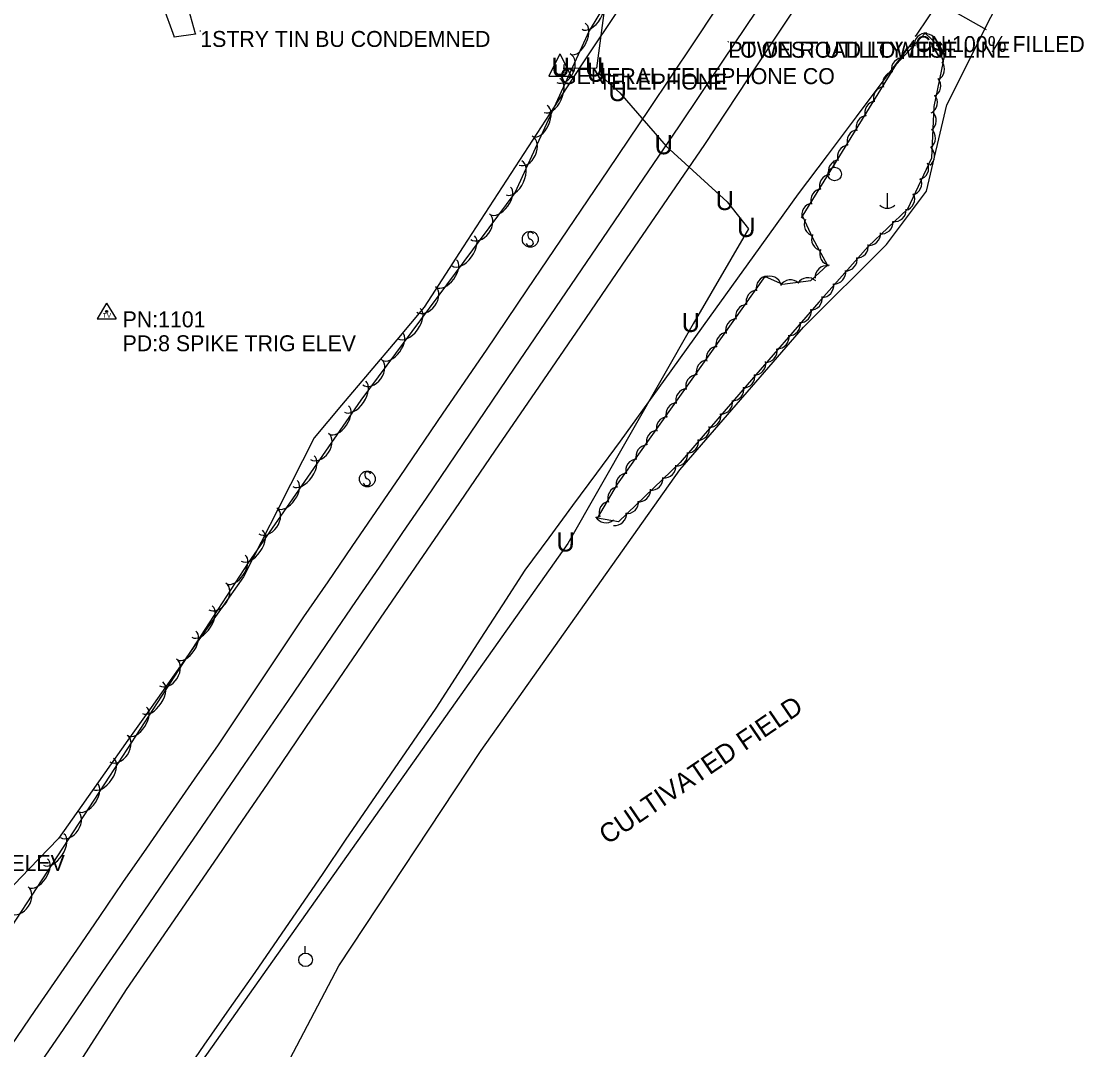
# Model space of a CAD drawing. Extents: x 1451369 to 1458940, y 1868647 to 1875095.
# Drawn here: x 1454865 to 1455198.2, y 1872001.9 to 1872324.4 of the extents above; entities that cross this region are included whole.
import ezdxf

# ---------------------------------------------------------------- set-up
doc = ezdxf.new("R2010")
doc.units = 0
for name, color, linetype in [('Default', 7, 'Continuous'), ('E_Const Align', 7, 'Continuous'), ('E_No Plot', 7, 'Continuous'), ('E_PL and Hook', 7, 'Continuous'), ('E_Property Line', 7, 'Continuous'), ('E_Proposed ROW and Easements', 7, 'Continuous'), ('E_Row Point', 7, 'Continuous'), ('E_ROW Point Number', 7, 'Continuous'), ('E_Station Offset', 7, 'Continuous'), ('E_Survey Point Number', 7, 'Continuous'), ('E_Tract Number', 7, 'Continuous'), ('S_EDGE_PAVEMENT', 7, 'Continuous'), ('S_ELECTRIC_UTILITIES_ANNOT', 7, 'Continuous'), ('S_EXIST_ROW', 7, 'Continuous'), ('S_MISC_BOUNDARY', 7, 'Continuous'), ('S_MISC_BOUNDARY_ANNOT', 7, 'Continuous'), ('S_PAVEMENT_CROWN', 7, 'Continuous'), ('S_SECONDARY_CTL_ANNOT', 7, 'Continuous'), ('S_SIDE_DRAIN_ANNOT', 7, 'Continuous'), ('S_SIGN', 7, 'Continuous'), ('S_SURVEY_TEXT_ANNOT', 7, 'Continuous'), ('S_TRAILS', 7, 'Continuous'), ('S_UNDERGROUND_CABLE_ANNOT', 7, 'Continuous'), ('S_UTILITY_POLE_ANNOT', 7, 'Continuous')]:
    doc.layers.add(name, color=color, linetype=linetype)

msp = doc.modelspace()

# ---------------------------------------------------------------- linework, layer by layer
at = {"layer": 'E_Const Align'}
for p, q in [((1455119.98, 1872278.62), (1455119.98, 1872280.72)), ((1455136.55, 1872270.43), (1455136.55, 1872265.7)), ((1454954.04, 1872032.19), (1454954.04, 1872034.3))]:
    msp.add_line(p, q, dxfattribs=at)
for centre in [(1455120.1, 1872276.47), (1454954.16, 1872030.05)]:
    msp.add_circle(centre, 2.13, dxfattribs=at)
msp.add_arc((1455136.61, 1872269.13), 3.41, 226.3972, 313.6028, dxfattribs=at)
at = {"layer": 'E_No Plot'}
msp.add_lwpolyline([(1455086.75, 1872317.95), (1455086.75, 1872318), (1455086.75, 1872317.95), (1455086.7, 1872317.95), (1455086.75, 1872317.95), (1455086.75, 1872317.9), (1455086.75, 1872317.95), (1455086.8, 1872317.95)], dxfattribs=at)
at = {"layer": 'E_PL and Hook'}
msp.add_line((1455157.21, 1872337.28), (1455145.4, 1872319.72), dxfattribs=at)
at = {"layer": 'E_Property Line'}
for p, q in [((1454919.62, 1872320.41), (1454916.52, 1872331.87)), ((1454909.24, 1872329.5), (1454912.94, 1872319.5)), ((1454912.94, 1872319.5), (1454919.62, 1872320.41))]:
    msp.add_line(p, q, dxfattribs=at)
at = {"layer": 'E_Proposed ROW and Easements'}
for points in [[(1454921.14, 1872321.33), (1454921.14, 1872321.38), (1454921.14, 1872321.33), (1454921.09, 1872321.33), (1454921.14, 1872321.33), (1454921.14, 1872321.28), (1454921.14, 1872321.33), (1454921.19, 1872321.33)], [(1455086.75, 1872317.95), (1455086.75, 1872318), (1455086.75, 1872317.95), (1455086.7, 1872317.95), (1455086.75, 1872317.95), (1455086.75, 1872317.9), (1455086.75, 1872317.95), (1455086.8, 1872317.95)]]:
    msp.add_lwpolyline(points, dxfattribs=at)
at = {"layer": 'E_Row Point'}
for points in [[(1454919.62, 1872320.41), (1454919.62, 1872320.46), (1454919.62, 1872320.41), (1454919.57, 1872320.41), (1454919.62, 1872320.41), (1454919.62, 1872320.36), (1454919.62, 1872320.41), (1454919.67, 1872320.41)], [(1454912.94, 1872319.5), (1454912.94, 1872319.55), (1454912.94, 1872319.5), (1454912.89, 1872319.5), (1454912.94, 1872319.5), (1454912.94, 1872319.45), (1454912.94, 1872319.5), (1454912.99, 1872319.5)]]:
    msp.add_lwpolyline(points, dxfattribs=at)
at = {"layer": 'E_ROW Point Number'}
for points in [[(1455062.48, 1872353.46), (1455043.07, 1872321.41), (1455019.75, 1872270.59), (1454971.46, 1872205.53), (1454936.2, 1872154.58), (1454892.72, 1872087.65), (1454838.97, 1872005.51)], [(1455109.68, 1872262.73), (1455139.45, 1872310.97), (1455148.48, 1872320.63), (1455152.34, 1872316.99), (1455154.17, 1872311.72), (1455151.15, 1872297.6), (1455150.43, 1872281.44), (1455142.98, 1872265.48), (1455130.56, 1872253.72), (1455115.11, 1872236.24), (1455092.67, 1872210.37), (1455071.63, 1872185.99), (1455052.32, 1872167.38), (1455045.77, 1872168.52), (1455051.95, 1872179.17), (1455098.31, 1872244.36), (1455103.7, 1872241.96), (1455112.65, 1872243.1), (1455117.86, 1872247.92), (1455113.28, 1872256.4), (1455110.15, 1872263.11)]]:
    msp.add_lwpolyline(points, dxfattribs=at)
for centre, major_axis, ratio, start_param, end_param in [((1455043.9, 1872326.88), (3.04, 5.01), 0.55061, 3.142085, 6.283677), ((1455039.58, 1872318.89), (2.23, 4.86), 0.540644, 3.141593, 6.283185), ((1455148.75, 1872317.02), (1.36, -3.38), 0.999281, 2.692526, 4.465726), ((1455148.74, 1872316.77), (-2.49, -2.66), 0.999283, 2.250379, 4.023579), ((1455145.19, 1872313.11), (1.36, -3.38), 0.999281, 2.692526, 4.465726), ((1455150.83, 1872313.32), (3.27, 1.62), 0.998167, 5.271173, 7.044373), ((1455035.04, 1872309.63), (2.07, 4.5), 0.685241, 3.141593, 6.283185), ((1455141.5, 1872309.27), (1.36, -3.38), 0.999281, 2.692526, 4.465726), ((1455150.93, 1872309.31), (0.76, 3.56), 0.999905, 3.825789, 5.598989), ((1455138.8, 1872304.92), (-0.75, -3.56), 0.99986, 3.481457, 5.254657), ((1455031.42, 1872301.11), (2.45, 5.33), 0.550024, 3.141593, 6.283185), ((1455135.94, 1872300.29), (-0.75, -3.56), 0.99986, 3.481457, 5.254657), ((1455149.74, 1872304.11), (0.76, 3.56), 0.999905, 3.825789, 5.598989), ((1455148.71, 1872298.92), (0.76, 3.56), 0.999905, 3.825789, 5.598989), ((1455027.72, 1872293.05), (2.23, 4.86), 0.540644, 3.141593, 6.283185), ((1455133.19, 1872295.76), (-0.75, -3.56), 0.99986, 3.481457, 5.254657), ((1455130.48, 1872291.22), (-0.75, -3.56), 0.99986, 3.481457, 5.254657), ((1455148.32, 1872293.2), (0.16, 3.64), 0.999925, 3.825789, 5.598989), ((1455127.61, 1872286.72), (-0.75, -3.56), 0.99986, 3.481457, 5.254657), ((1455148.08, 1872287.77), (0.16, 3.64), 0.999925, 3.825789, 5.598989), ((1455023.19, 1872283.8), (2.07, 4.5), 0.685241, 3.141593, 6.283185), ((1455124.62, 1872281.94), (-0.75, -3.56), 0.99986, 3.481457, 5.254657), ((1455147.79, 1872282.13), (0.16, 3.64), 0.999925, 3.825789, 5.598989), ((1455019.57, 1872275.27), (2.45, 5.33), 0.550024, 3.141593, 6.283185), ((1455121.76, 1872277.31), (-0.75, -3.56), 0.99986, 3.481457, 5.254657), ((1455145.93, 1872278.28), (1.54, 3.3), 0.999883, 3.825789, 5.598989), ((1455119.01, 1872272.77), (-0.75, -3.56), 0.99986, 3.481457, 5.254657), ((1455143.77, 1872273.46), (1.54, 3.3), 0.999883, 3.825789, 5.598989), ((1455015.25, 1872268.09), (3.19, 4.29), 0.540655, 3.141593, 6.283185), ((1455116.29, 1872268.24), (-0.75, -3.56), 0.99986, 3.481457, 5.254657), ((1455141.56, 1872268.64), (1.54, 3.3), 0.999883, 3.825789, 5.598989), ((1455113.43, 1872263.74), (-0.75, -3.56), 0.99986, 3.481457, 5.254657), ((1455008.9, 1872259.97), (2.95, 3.98), 0.685254, 3.141593, 6.283185), ((1455138.86, 1872265.2), (2.65, 2.51), 0.999871, 3.825789, 5.598989), ((1455114.19, 1872260.67), (-1.49, -3.32), 0.999957, 4.685306, 6.458507), ((1455134.74, 1872261.34), (2.65, 2.51), 0.999871, 3.825789, 5.598989), ((1455003.6, 1872252.38), (3.5, 4.71), 0.550034, 3.141593, 6.283185), ((1455116.49, 1872256.07), (1.73, -3.21), 0.999986, 3.825789, 5.598989), ((1455130.82, 1872257.73), (2.65, 2.51), 0.999871, 3.825789, 5.598989), ((1455127.02, 1872253.73), (2.41, 2.73), 0.999871, 3.825789, 5.598989), ((1455119.06, 1872251.45), (1.73, -3.21), 0.999986, 3.825789, 5.598989), ((1455123.53, 1872249.73), (2.41, 2.73), 0.999871, 3.825789, 5.598989), ((1454998.31, 1872245.26), (3.19, 4.29), 0.540655, 3.141593, 6.283185), ((1455117.61, 1872244.07), (-2.67, -2.47), 0.999872, 3.825789, 5.598989), ((1455099.13, 1872240.8), (-2.16, -2.93), 0.999873, 3.843327, 5.616528), ((1455099.83, 1872240.77), (-1.3, -3.4), 0.995414, 2.200916, 3.974117), ((1455106.25, 1872239.64), (-3.61, -0.46), 0.999924, 3.825789, 5.598989), ((1455111.65, 1872240.32), (-3.61, -0.46), 0.999924, 3.825789, 5.598989), ((1455119.93, 1872245.65), (2.41, 2.73), 0.999871, 3.825789, 5.598989), ((1454991.96, 1872237.14), (2.95, 3.98), 0.685254, 3.141593, 6.283185), ((1455095.98, 1872236.49), (-2.16, -2.93), 0.999873, 3.843327, 5.616528), ((1455116.16, 1872241.45), (2.41, 2.73), 0.999871, 3.825789, 5.598989), ((1455112.56, 1872237.47), (2.39, 2.75), 0.999871, 3.825789, 5.598989), ((1454986.65, 1872229.55), (3.5, 4.71), 0.550034, 3.141593, 6.283185), ((1455092.68, 1872231.91), (-2.16, -2.93), 0.999873, 3.843327, 5.616528), ((1455109.15, 1872233.44), (2.39, 2.75), 0.999871, 3.825789, 5.598989), ((1455089.53, 1872227.48), (-2.16, -2.93), 0.999873, 3.843327, 5.616528), ((1455105.71, 1872229.41), (2.39, 2.75), 0.999871, 3.825789, 5.598989), ((1454981.37, 1872222.43), (3.19, 4.29), 0.540655, 3.141593, 6.283185), ((1455086.48, 1872223.14), (-2.16, -2.93), 0.999873, 3.843327, 5.616528), ((1455102.14, 1872225.3), (2.39, 2.75), 0.999871, 3.825789, 5.598989), ((1455083.48, 1872218.79), (-2.16, -2.93), 0.999873, 3.843327, 5.616528), ((1455098.41, 1872221.05), (2.39, 2.75), 0.999871, 3.825789, 5.598989), ((1454975.02, 1872214.31), (2.95, 3.98), 0.685254, 3.141593, 6.283185), ((1455080.33, 1872214.48), (-2.16, -2.93), 0.999873, 3.843327, 5.616528), ((1455094.86, 1872217.07), (2.39, 2.75), 0.999871, 3.825789, 5.598989), ((1455077.03, 1872209.9), (-2.16, -2.93), 0.999873, 3.843327, 5.616528), ((1455091.46, 1872213.03), (2.39, 2.75), 0.999871, 3.825789, 5.598989), ((1454969.67, 1872206.67), (3.34, 4.83), 0.550033, 3.141593, 6.283185), ((1455073.87, 1872205.47), (-2.16, -2.93), 0.999873, 3.843327, 5.616528), ((1455088.01, 1872208.99), (2.38, 2.76), 0.999871, 3.825789, 5.598989), ((1454964.62, 1872199.37), (3.04, 4.4), 0.540653, 3.141593, 6.283185), ((1455070.83, 1872201.13), (-2.16, -2.93), 0.999873, 3.843327, 5.616528), ((1455084.45, 1872204.87), (2.38, 2.76), 0.999871, 3.825789, 5.598989), ((1455067.83, 1872196.78), (-2.16, -2.93), 0.999873, 3.843327, 5.616528), ((1455080.74, 1872200.62), (2.38, 2.76), 0.999871, 3.825789, 5.598989), ((1455077.2, 1872196.63), (2.38, 2.76), 0.999871, 3.825789, 5.598989), ((1454958.55, 1872191.05), (2.82, 4.07), 0.685252, 3.141593, 6.283185), ((1455064.68, 1872192.47), (-2.16, -2.93), 0.999873, 3.843327, 5.616528), ((1455073.8, 1872192.58), (2.38, 2.76), 0.999871, 3.825789, 5.598989), ((1455061.38, 1872187.89), (-2.16, -2.93), 0.999873, 3.843327, 5.616528), ((1454953.49, 1872183.29), (3.34, 4.83), 0.550033, 3.141593, 6.283185), ((1455058.22, 1872183.46), (-2.16, -2.93), 0.999873, 3.843327, 5.616528), ((1455070.37, 1872188.54), (2.38, 2.76), 0.999871, 3.825789, 5.598989), ((1455066.68, 1872184.87), (2.62, 2.53), 0.999871, 3.825789, 5.598989), ((1454948.44, 1872176), (3.04, 4.4), 0.540653, 3.141593, 6.283185), ((1455055.18, 1872179.11), (-2.16, -2.93), 0.999873, 3.843327, 5.616528), ((1455062.6, 1872180.98), (2.62, 2.53), 0.999871, 3.825789, 5.598989), ((1455052.58, 1872174.81), (-2.84, -2.28), 0.999859, 4.194335, 5.967535), ((1455058.7, 1872177.33), (2.62, 2.53), 0.999871, 3.825789, 5.598989), ((1455049.84, 1872170.23), (-2.84, -2.28), 0.999859, 4.194335, 5.967535), ((1455054.95, 1872173.61), (2.62, 2.53), 0.999871, 3.825789, 5.598989), ((1454942.37, 1872167.68), (2.82, 4.07), 0.685252, 3.141593, 6.283185), ((1455051.16, 1872169.91), (2.62, 2.53), 0.999871, 3.825789, 5.598989), ((1455048.31, 1872170.75), (3.59, -0.62), 0.999962, 3.825789, 5.598989), ((1454937.31, 1872159.92), (3.34, 4.83), 0.550033, 3.141593, 6.283185), ((1454932.32, 1872152.51), (2.91, 4.48), 0.540651, 3.141593, 6.283185), ((1454926.49, 1872144.01), (2.7, 4.16), 0.68525, 3.141593, 6.283185), ((1454921.67, 1872136.11), (3.2, 4.92), 0.550031, 3.141593, 6.283185), ((1454916.84, 1872128.67), (2.91, 4.48), 0.540651, 3.141593, 6.283185), ((1454911.01, 1872120.17), (2.7, 4.16), 0.68525, 3.141593, 6.283185), ((1454906.18, 1872112.27), (3.2, 4.92), 0.550031, 3.141593, 6.283185), ((1454901.35, 1872104.83), (2.91, 4.48), 0.540651, 3.141593, 6.283185), ((1454895.52, 1872096.33), (2.7, 4.16), 0.68525, 3.141593, 6.283185), ((1454890.7, 1872088.43), (3.21, 4.91), 0.550031, 3.141593, 6.283185), ((1454885.84, 1872081.01), (2.93, 4.47), 0.540652, 3.141593, 6.283185), ((1454879.98, 1872072.54), (2.71, 4.15), 0.68525, 3.141593, 6.283185), ((1454875.13, 1872064.65), (3.21, 4.91), 0.550031, 3.141593, 6.283185), ((1454870.27, 1872057.23), (2.93, 4.47), 0.540652, 3.141593, 6.283185), ((1454864.42, 1872048.75), (2.71, 4.15), 0.68525, 3.141593, 6.283185)]:
    msp.add_ellipse(centre, major_axis=major_axis, ratio=ratio, start_param=start_param, end_param=end_param, dxfattribs=at)
at = {"layer": 'E_Station Offset'}
for p, q in [((1454891.77, 1872236.01), (1454888.76, 1872231.05)), ((1454891.77, 1872236.01), (1454894.71, 1872231.05)), ((1454888.76, 1872231.05), (1454894.71, 1872231.05))]:
    msp.add_line(p, q, dxfattribs=at)
for radius in [0.311, 0.183, 0.103]:
    msp.add_circle((1454891.77, 1872233.4), radius, dxfattribs=at)
at = {"layer": 'E_Survey Point Number'}
for p, q in [((1455047.85, 1872327.75), (1455045.4, 1872309.63)), ((1455033.95, 1872314.2), (1455030.43, 1872307.11)), ((1455033.95, 1872314.2), (1455037.44, 1872307.11)), ((1455032.75, 1872308.35), (1455032.75, 1872310.79)), ((1455035.11, 1872310.79), (1455035.11, 1872308.35)), ((1455030.43, 1872307.11), (1455037.44, 1872307.11)), ((1455033.37, 1872307.69), (1455032.75, 1872308.35)), ((1455034.57, 1872307.69), (1455033.37, 1872307.69)), ((1455035.11, 1872308.35), (1455034.57, 1872307.69)), ((1455045.4, 1872309.63), (1455034.9, 1872309.52)), ((1455045.98, 1872307.95), (1455052.76, 1872301.89)), ((1455052.76, 1872301.89), (1455067.23, 1872285.22)), ((1455067.23, 1872285.22), (1455086.37, 1872267.71)), ((1455086.37, 1872267.71), (1455093.12, 1872259.28)), ((1455093.12, 1872259.28), (1455075.72, 1872229.49)), ((1455075.72, 1872229.49), (1455036.45, 1872160.65)), ((1455036.45, 1872160.65), (1454894.46, 1871959.88))]:
    msp.add_line(p, q, dxfattribs=at)
at = {"layer": 'E_Tract Number'}
msp.add_lwpolyline([(1455145.4, 1872319.72), (1455145.4, 1872319.77), (1455145.4, 1872319.72), (1455145.35, 1872319.72), (1455145.4, 1872319.72), (1455145.4, 1872319.67), (1455145.4, 1872319.72), (1455145.45, 1872319.72)], dxfattribs=at)
at = {"layer": 'S_EDGE_PAVEMENT'}
for points in [[(1455082.86, 1872328.15), (1455075.85, 1872317.66), (1455068.85, 1872307.17), (1455061.85, 1872296.68), (1455049.09, 1872277.83), (1455036.33, 1872258.97), (1455023.56, 1872240.12), (1455010.8, 1872221.26), (1454997.26, 1872201.47), (1454983.72, 1872181.67), (1454976.18, 1872170.65), (1454968.64, 1872159.62), (1454961.1, 1872148.6), (1454953.56, 1872137.57), (1454940.13, 1872117.53), (1454926.71, 1872097.49), (1454919.22, 1872086.68), (1454911.73, 1872075.87), (1454904.25, 1872065.07), (1454896.76, 1872054.26), (1454889.52, 1872043.66), (1454882.28, 1872033.07), (1454869.28, 1872014.16), (1454856.27, 1871995.25)], [(1455106.55, 1872326.88), (1455092.89, 1872306.29), (1455079.23, 1872285.69), (1455066.27, 1872266.77), (1455053.31, 1872247.84), (1455040.35, 1872228.91), (1455027.39, 1872209.98), (1455013.43, 1872189.56), (1454999.47, 1872169.15), (1454992.16, 1872158.48), (1454984.85, 1872147.82), (1454977.54, 1872137.15), (1454970.23, 1872126.48), (1454963.2, 1872116.14), (1454956.16, 1872105.8), (1454949.13, 1872095.45), (1454942.1, 1872085.11), (1454934.3, 1872073.71), (1454926.5, 1872062.32), (1454918.71, 1872050.92), (1454910.91, 1872039.53), (1454897.92, 1872020.78), (1454886.12, 1872002.39), (1454874.32, 1871984)]]:
    msp.add_lwpolyline(points, dxfattribs=at)
at = {"layer": 'S_EXIST_ROW'}
for points in [[(1455067.63, 1872351.06), (1455053.98, 1872330.57), (1455040.32, 1872310.08), (1455028.09, 1872291.25), (1455015.85, 1872272.42), (1455003.61, 1872253.59), (1454991.38, 1872234.76), (1454982.74, 1872224.5), (1454974.11, 1872214.23), (1454965.48, 1872203.97), (1454956.84, 1872193.71), (1454945.77, 1872171.92), (1454934.69, 1872150.13), (1454927.44, 1872139.88), (1454920.2, 1872129.63), (1454912.95, 1872119.39), (1454905.71, 1872109.14), (1454898.46, 1872098.89), (1454891.21, 1872088.65), (1454883.97, 1872078.4), (1454876.72, 1872068.15), (1454867.48, 1872058.62), (1454858.23, 1872049.09)], [(1455144.92, 1872318.5), (1455135.86, 1872306.44), (1455126.81, 1872294.38), (1455117.75, 1872282.32), (1455108.7, 1872270.26), (1455094.74, 1872250.88), (1455080.78, 1872231.51), (1455066.82, 1872212.13), (1455052.86, 1872192.75), (1455045.38, 1872182.62), (1455037.9, 1872172.48), (1455030.42, 1872162.35), (1455022.93, 1872152.22), (1455015.95, 1872141.41), (1455008.96, 1872130.61), (1455001.98, 1872119.8), (1454994.99, 1872109), (1454987.9, 1872098.63), (1454980.81, 1872088.27), (1454973.72, 1872077.9), (1454966.63, 1872067.54), (1454959.54, 1872057.17), (1454952.45, 1872046.81), (1454945.37, 1872036.44), (1454938.28, 1872026.08), (1454930.24, 1872014.67), (1454922.21, 1872003.26), (1454908.47, 1871983.1)]]:
    msp.add_lwpolyline(points, dxfattribs=at)
at = {"layer": 'S_MISC_BOUNDARY'}
msp.add_lwpolyline([(1454968.19, 1871712.29), (1454955.87, 1871795.22), (1454948.77, 1871830.35), (1454936.8, 1871870.9), (1454929.34, 1871910.01), (1454929.36, 1871947.22), (1454941.55, 1871984.39), (1454964.58, 1872028.21), (1455009.26, 1872095.69), (1455071.49, 1872183.66), (1455110.31, 1872228.42), (1455136.38, 1872254.42), (1455148.95, 1872271.07), (1455155.24, 1872298.12), (1455196.69, 1872380.74)], dxfattribs=at)
at = {"layer": 'S_PAVEMENT_CROWN'}
msp.add_lwpolyline([(1455098.91, 1872332.78), (1455085.14, 1872312.19), (1455071.37, 1872291.6), (1455058.41, 1872272.6), (1455045.46, 1872253.6), (1455032.51, 1872234.61), (1455019.56, 1872215.61), (1455005.77, 1872195.22), (1454991.98, 1872174.82), (1454984.59, 1872164.01), (1454977.2, 1872153.2), (1454969.8, 1872142.38), (1454962.41, 1872131.57), (1454948.68, 1872111.42), (1454934.95, 1872091.27), (1454927.52, 1872080.43), (1454920.09, 1872069.59), (1454912.66, 1872058.75), (1454905.23, 1872047.91), (1454897.86, 1872037.14), (1454890.49, 1872026.36), (1454878.1, 1872008.25), (1454865.71, 1871990.14)], dxfattribs=at)
at = {"layer": 'S_SIGN'}
for centre in [(1455024.64, 1872256.02), (1454973.53, 1872180.85)]:
    msp.add_circle(centre, 2.49, dxfattribs=at)
for centre, radius, start, end in [((1455025.33, 1872257.35), 1.5, 167.1196, 241.9813), ((1455024.72, 1872257.29), 0.95, 16.5258, 156.8957), ((1455024.49, 1872255.2), 1.28, 204.641, 335.359), ((1455024.23, 1872254.68), 1.4, 358.6529, 73.7063), ((1454974.21, 1872182.18), 1.5, 167.1196, 241.9813), ((1454973.6, 1872182.12), 0.95, 16.5258, 156.8957), ((1454973.11, 1872179.51), 1.4, 358.6529, 73.7063), ((1454973.37, 1872180.03), 1.28, 204.641, 335.359)]:
    msp.add_arc(centre, radius, start, end, dxfattribs=at)
at = {"layer": 'S_TRAILS'}
msp.add_lwpolyline([(1455120.4, 1872348.51), (1455167.63, 1872321.76)], dxfattribs=at)

# ---------------------------------------------------------------- texts
at = {"layer": 'Default'}
for p in [(1455031.27, 1872306.97), (1455041.77, 1872307.08), (1455042.35, 1872305.4), (1455049.13, 1872299.34), (1455063.6, 1872282.67), (1455082.74, 1872265.17), (1455089.49, 1872256.74), (1455072.09, 1872226.94), (1455032.82, 1872158.1)]:
    msp.add_text('U', height=6, rotation=360, dxfattribs=at).set_placement(p)
at = {"layer": 'E_Station Offset'}
msp.add_text('TV', height=1.5, rotation=360, dxfattribs=at).set_placement((1454890.56, 1872231.39))
at = {"layer": 'S_ELECTRIC_UTILITIES_ANNOT'}
msp.add_text('PT ON ROAD LOWEST LINE', height=5, dxfattribs=at).set_placement((1455086.75, 1872312.95))
at = {"layer": 'S_MISC_BOUNDARY_ANNOT'}
msp.add_text('CULTIVATED FIELD', height=6.0005, rotation=34.3129, dxfattribs=at).set_placement((1455048.83, 1872066.02))
at = {"layer": 'S_SECONDARY_CTL_ANNOT'}
for s, p in [('PN:1101', (1454896.77, 1872228.4)), ('PD:8 SPIKE TRIG ELEV', (1454896.77, 1872220.9)), ('PD:8 SPIKE TRIG ELEV', (1454805.46, 1872057.93))]:
    msp.add_text(s, height=5, dxfattribs=at).set_placement(p)
at = {"layer": 'S_SIDE_DRAIN_ANNOT'}
msp.add_text('CN:100% FILLED', height=5, dxfattribs=at).set_placement((1455145.4, 1872314.72))
at = {"layer": 'S_SURVEY_TEXT_ANNOT'}
for s, p in [('1STRY TIN BU CONDEMNED', (1454921.14, 1872316.33)), ('LOWEST UTILITY LINE', (1455086.75, 1872312.95))]:
    msp.add_text(s, height=5, dxfattribs=at).set_placement(p)
at = {"layer": 'S_UNDERGROUND_CABLE_ANNOT'}
msp.add_text('TELEPHONE', height=5, dxfattribs=at).set_placement((1455045.98, 1872302.95))
at = {"layer": 'S_UTILITY_POLE_ANNOT'}
msp.add_text('GENERAL TELEPHONE CO', height=5, dxfattribs=at).set_placement((1455033.95, 1872304.67))

doc.saveas('drawing.dxf')
